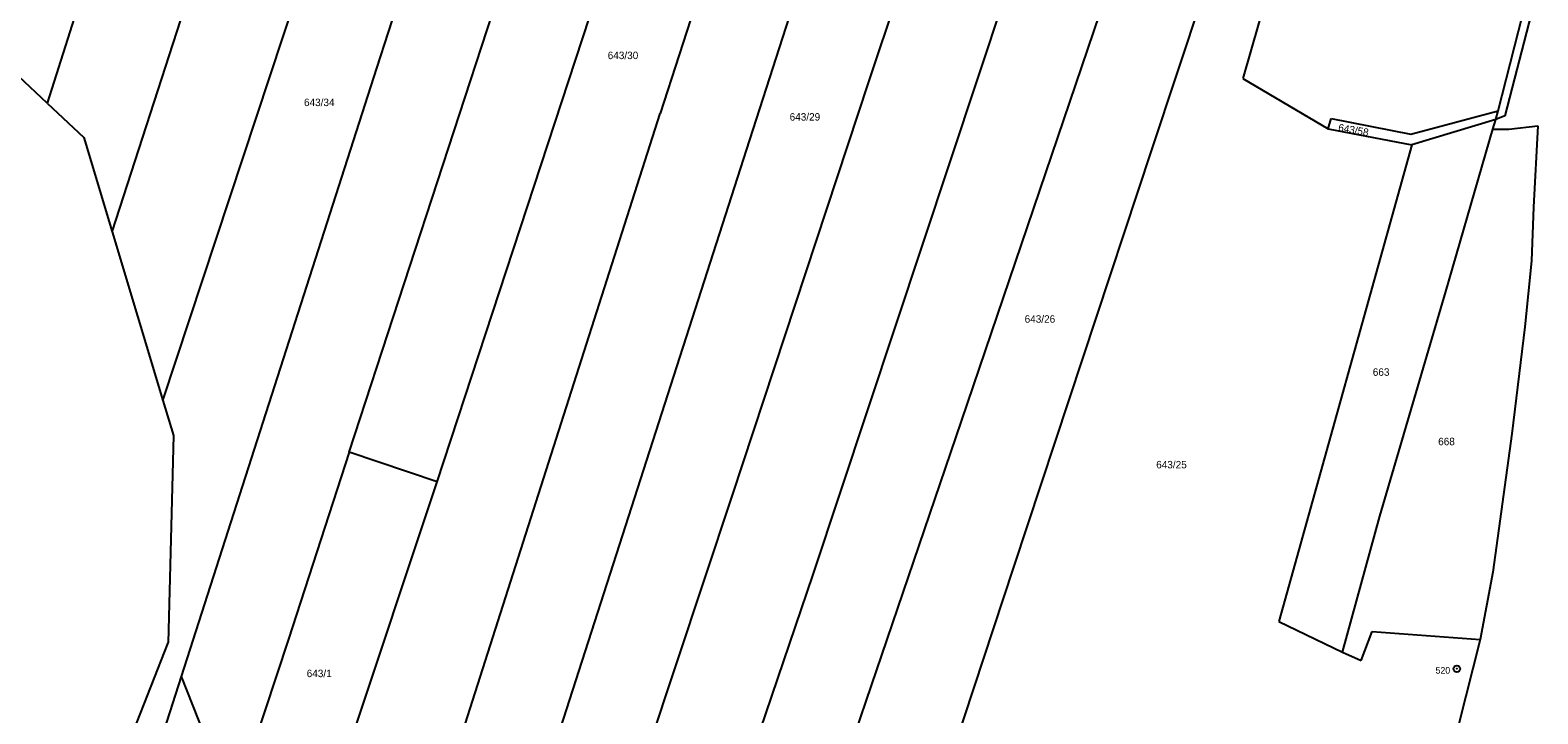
# Model space of a CAD drawing. Extents: x -701211 to -698780, y -1014269 to -1012378.
# Drawn here: x -700113.3 to -699770.2, y -1014024.8 to -1013869.1 of the extents above; entities that cross this region are included whole.
import ezdxf
from ezdxf.enums import TextEntityAlignment as Align

# ---------------------------------------------------------------- set-up
doc = ezdxf.new("R2010")
doc.units = 0
doc.header["$LTSCALE"] = 0.68
doc.layers.add('1', color=7, linetype='Continuous', lineweight=25)
doc.layers.add('8', color=7, linetype='Continuous', lineweight=25)
doc.layers.add('2', color=7, linetype='Continuous')

msp = doc.modelspace()

# ---------------------------------------------------------------- linework, layer by layer
at = {"layer": '1'}
for p, q in [((-699925.56, -1013749.95), (-699969.9, -1013888.1)), ((-699949.52, -1013894.1), (-699905.62, -1013757.93)), ((-699884.55, -1013766.36), (-699922.52, -1013880.91)), ((-700040.69, -1013965.22), (-699981.65, -1013784.09)), ((-700079.75, -1013792.27), (-700109.42, -1013885.76)), ((-700020.69, -1013971.93), (-699961.55, -1013791.76)), ((-699823.25, -1013790.89), (-699858.1, -1013896.35)), ((-699812.8, -1013795.07), (-699837.38, -1013880.14)), ((-700094.62, -1013915.06), (-700057.59, -1013800.71)), ((-700034.38, -1013877.75), (-700014.85, -1013817)), ((-699881.66, -1013831.74), (-699935.16, -1013993.03)), ((-700083.1, -1013953.47), (-700044.37, -1013836.12)), ((-699901.37, -1013958.16), (-699859.92, -1013836.1)), ((-699779.27, -1013887.48), (-699772.82, -1013862.12)), ((-699771.73, -1013865.51), (-699777.75, -1013888.6)), ((-700109.42, -1013885.76), (-700126.53, -1013869.72)), ((-700078.87, -1014016.26), (-700034.38, -1013877.75)), ((-699922.52, -1013880.91), (-699953.57, -1013975)), ((-699837.38, -1013880.14), (-699817.97, -1013891.6)), ((-700109.42, -1013885.76), (-700101.06, -1013893.59)), ((-700030.79, -1014078.6), (-699969.9, -1013888.1)), ((-699799.09, -1013892.81), (-699779.27, -1013887.48)), ((-699779.77, -1013889.48), (-699779.27, -1013887.48)), ((-699777.75, -1013888.6), (-699779.77, -1013889.48)), ((-699817.97, -1013891.6), (-699817.25, -1013889.27)), ((-699817.97, -1013891.6), (-699798.88, -1013895.22)), ((-699817.25, -1013889.27), (-699799.09, -1013892.81)), ((-699779.77, -1013889.48), (-699798.88, -1013895.22)), ((-699791.18, -1013928.65), (-699780.44, -1013891.63)), ((-699780.44, -1013891.63), (-699779.77, -1013889.48)), ((-699780.44, -1013891.63), (-699776.83, -1013891.65)), ((-699776.83, -1013891.65), (-699770.22, -1013890.88)), ((-699770.22, -1013890.88), (-699771.19, -1013909.39)), ((-700101.06, -1013893.59), (-700094.62, -1013915.06)), ((-699979.87, -1013988.51), (-699949.52, -1013894.1)), ((-699798.88, -1013895.22), (-699829.14, -1014003.78)), ((-699858.1, -1013896.35), (-699889.52, -1013991.39)), ((-699771.19, -1013909.39), (-699771.66, -1013921.67)), ((-700094.62, -1013915.06), (-700083.1, -1013953.47)), ((-699771.66, -1013921.67), (-699773.21, -1013936.68)), ((-699806.21, -1013979.8), (-699791.18, -1013928.65)), ((-699773.21, -1013936.68), (-699776.12, -1013961.03)), ((-700083.1, -1013953.47), (-700080.71, -1013961.43)), ((-699942.98, -1014080.51), (-699901.37, -1013958.16)), ((-700080.71, -1013961.43), (-700081.91, -1014008.58)), ((-699776.12, -1013961.03), (-699780.44, -1013992.5)), ((-700040.69, -1013965.22), (-700054.52, -1014007.78)), ((-700020.69, -1013971.93), (-700040.69, -1013965.22)), ((-700054.6, -1014073.85), (-700020.69, -1013971.93)), ((-699953.57, -1013975), (-699985.36, -1014070.79)), ((-699814.67, -1014010.74), (-699806.21, -1013979.8)), ((-700010.73, -1014084.51), (-699979.87, -1013988.51)), ((-699889.52, -1013991.39), (-699920.86, -1014086.25)), ((-699935.16, -1013993.03), (-699963.2, -1014075.19)), ((-699780.44, -1013992.5), (-699783.31, -1014007.83)), ((-699829.14, -1014003.78), (-699814.67, -1014010.74)), ((-700103.57, -1014063.88), (-700081.91, -1014008.58)), ((-700054.52, -1014007.78), (-700067.12, -1014045.95)), ((-699810.42, -1014012.6), (-699807.9, -1014006.01)), ((-699807.9, -1014006.01), (-699783.31, -1014007.83)), ((-699783.31, -1014007.83), (-699788.25, -1014027.36)), ((-699814.67, -1014010.74), (-699810.42, -1014012.6)), ((-700094.24, -1014064.11), (-700078.87, -1014016.26)), ((-700067.12, -1014045.95), (-700078.87, -1014016.26))]:
    msp.add_line(p, q, dxfattribs=at)
at = {"layer": '8'}
for radius in [0.75, 0.03]:
    msp.add_circle((-699788.66, -1014014.5098), radius, dxfattribs=at)

# ---------------------------------------------------------------- texts
at = {"layer": '2'}
for s, p in [('643/30', (-699981.87, -1013875.715)), ('643/34', (-700050.98, -1013886.415)), ('643/29', (-699940.47, -1013889.715)), ('643/26', (-699887, -1013935.735)), ('663', (-699807.78, -1013947.815)), ('668', (-699792.9, -1013963.625)), ('643/25', (-699857.06, -1013968.895))]:
    msp.add_text(s, height=1.7, dxfattribs=at).set_placement(p)
msp.add_text('643/58', height=1.7, rotation=350, dxfattribs=at).set_placement((-699812.3181, -1013892.6812), align=Align.CENTER)
msp.add_text('643/1', height=1.7, dxfattribs=at).set_placement((-700047.52, -1014016.425), align=Align.CENTER)
at = {"layer": '8'}
msp.add_text('520', height=1.5, dxfattribs=at).set_placement((-699790.159, -1014015.627), align=Align.RIGHT)

doc.saveas('drawing.dxf')
